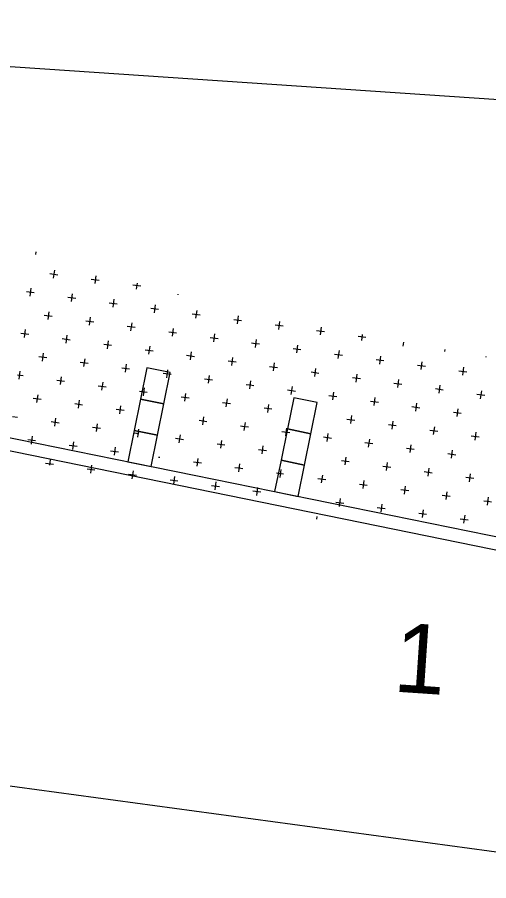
# Model space of a CAD drawing. Extents: x 1312564.5 to 1312581.5, y 1207298.4 to 1207309.4.
# Drawn here: x 1312577.003 to 1312577.548, y 1207303.846 to 1207304.843 of the extents above; entities that cross this region are included whole.
import ezdxf

# ---------------------------------------------------------------- set-up
doc = ezdxf.new("R2010")
doc.units = 0
for name, color, linetype in [('Level 15', 7, 'Continuous'), ('Level 2', 7, 'Continuous'), ('Level 20', 7, 'Continuous'), ('Level 3', 7, 'Continuous'), ('Level 4', 7, 'Continuous')]:
    doc.layers.add(name, color=color, linetype=linetype)

msp = doc.modelspace()

# ---------------------------------------------------------------- linework, layer by layer
at = {"layer": 'Level 15'}
msp.add_lwpolyline([(1312576.15065, 1207304.84261), (1312579.49796, 1207304.61698)], dxfattribs=at)
at = {"layer": 'Level 2'}
for p, q in [((1312576.95323, 1207304.36568), (1312579.00727, 1207303.94777)), ((1312579.00473, 1207303.93271), (1312576.95019, 1207304.35072))]:
    msp.add_line(p, q, dxfattribs=at)
for points in [[(1312577.14535, 1207304.40183), (1312577.17244, 1207304.39632), (1312577.17979, 1207304.43244), (1312577.1527, 1207304.43795)], [(1312577.138, 1207304.3657), (1312577.16509, 1207304.36019), (1312577.17244, 1207304.39632), (1312577.14535, 1207304.40183)], [(1312577.31505, 1207304.3673), (1312577.34215, 1207304.36179), (1312577.3495, 1207304.39791), (1312577.3224, 1207304.40342)], [(1312577.13065, 1207304.32958), (1312577.15774, 1207304.32407), (1312577.16509, 1207304.36019), (1312577.138, 1207304.3657)], [(1312577.3077, 1207304.33118), (1312577.3348, 1207304.32566), (1312577.34215, 1207304.36179), (1312577.31505, 1207304.3673)], [(1312577.30035, 1207304.29505), (1312577.32745, 1207304.28954), (1312577.3348, 1207304.32566), (1312577.3077, 1207304.33118)]]:
    msp.add_lwpolyline(points, close=True, dxfattribs=at)
at = {"layer": 'Level 3'}
msp.add_line((1312575.46594, 1207304.16215), (1312578.72454, 1207303.72084), dxfattribs=at)
at = {"layer": 'Level 4'}
for p, q in [((1312577.02429, 1207304.5717), (1312577.02389, 1207304.56865)), ((1312577.04585, 1207304.55063), (1312577.04463, 1207304.54149)), ((1312577.04067, 1207304.54667), (1312577.04981, 1207304.54545)), ((1312577.08857, 1207304.54026), (1312577.09771, 1207304.53904)), ((1312577.09375, 1207304.54421), (1312577.09253, 1207304.53508)), ((1312577.01869, 1207304.52989), (1312577.01747, 1207304.52075)), ((1312577.13647, 1207304.53384), (1312577.14561, 1207304.53262)), ((1312577.14134, 1207304.53547), (1312577.14043, 1207304.52867)), ((1312577.01352, 1207304.52593), (1312577.02265, 1207304.52471)), ((1312577.06142, 1207304.51952), (1312577.07055, 1207304.51829)), ((1312577.06659, 1207304.52347), (1312577.06537, 1207304.51434)), ((1312577.18843, 1207304.52301), (1312577.18833, 1207304.52225)), ((1312577.10932, 1207304.5131), (1312577.11845, 1207304.51188)), ((1312577.11449, 1207304.51706), (1312577.11327, 1207304.50792)), ((1312577.16239, 1207304.51064), (1312577.16117, 1207304.50151)), ((1312577.03426, 1207304.49877), (1312577.04339, 1207304.49755)), ((1312577.03944, 1207304.50273), (1312577.03821, 1207304.49359)), ((1312577.15722, 1207304.50669), (1312577.16635, 1207304.50546)), ((1312577.20512, 1207304.50027), (1312577.21425, 1207304.49905)), ((1312577.2103, 1207304.50423), (1312577.20907, 1207304.49509)), ((1312577.08216, 1207304.49236), (1312577.09129, 1207304.49114)), ((1312577.08734, 1207304.49631), (1312577.08611, 1207304.48718)), ((1312577.13524, 1207304.4899), (1312577.13401, 1207304.48077)), ((1312577.25302, 1207304.49386), (1312577.26215, 1207304.49264)), ((1312577.2582, 1207304.49781), (1312577.25697, 1207304.48868)), ((1312577.3061, 1207304.4914), (1312577.30487, 1207304.48227)), ((1312577.01228, 1207304.48199), (1312577.01106, 1207304.47285)), ((1312577.13006, 1207304.48594), (1312577.13919, 1207304.48472)), ((1312577.17796, 1207304.47953), (1312577.18709, 1207304.47831)), ((1312577.18314, 1207304.48349), (1312577.18191, 1207304.47435)), ((1312577.30092, 1207304.48744), (1312577.31005, 1207304.48622)), ((1312577.34882, 1207304.48103), (1312577.35795, 1207304.47981)), ((1312577.354, 1207304.48499), (1312577.35277, 1207304.47585)), ((1312577.0071, 1207304.47803), (1312577.01624, 1207304.47681)), ((1312577.055, 1207304.47162), (1312577.06414, 1207304.47039)), ((1312577.06018, 1207304.47557), (1312577.05896, 1207304.46644)), ((1312577.10808, 1207304.46916), (1312577.10686, 1207304.46002)), ((1312577.22586, 1207304.47312), (1312577.23499, 1207304.47189)), ((1312577.23104, 1207304.47707), (1312577.22981, 1207304.46794)), ((1312577.27894, 1207304.47066), (1312577.27771, 1207304.46152)), ((1312577.39672, 1207304.47462), (1312577.40585, 1207304.47339)), ((1312577.40159, 1207304.47631), (1312577.40067, 1207304.46944)), ((1312577.1029, 1207304.4652), (1312577.11204, 1207304.46398)), ((1312577.1508, 1207304.45879), (1312577.15994, 1207304.45756)), ((1312577.15598, 1207304.46274), (1312577.15476, 1207304.45361)), ((1312577.27376, 1207304.4667), (1312577.27833, 1207304.46609)), ((1312577.27833, 1207304.46609), (1312577.28289, 1207304.46548)), ((1312577.32166, 1207304.46029), (1312577.33079, 1207304.45906)), ((1312577.32684, 1207304.46424), (1312577.32562, 1207304.45511)), ((1312577.44916, 1207304.46744), (1312577.44857, 1207304.46302)), ((1312577.49679, 1207304.45897), (1312577.49647, 1207304.45661)), ((1312577.02784, 1207304.45087), (1312577.03698, 1207304.44965)), ((1312577.03302, 1207304.45483), (1312577.0318, 1207304.44569)), ((1312577.1987, 1207304.45237), (1312577.20784, 1207304.45115)), ((1312577.20388, 1207304.45633), (1312577.20266, 1207304.44719)), ((1312577.25178, 1207304.44991), (1312577.25056, 1207304.44078)), ((1312577.36956, 1207304.45387), (1312577.37869, 1207304.45265)), ((1312577.37474, 1207304.45783), (1312577.37352, 1207304.44869)), ((1312577.42264, 1207304.45141), (1312577.42142, 1207304.44228)), ((1312577.54446, 1207304.45086), (1312577.54437, 1207304.45019)), ((1312577.07574, 1207304.44446), (1312577.08488, 1207304.44324)), ((1312577.08092, 1207304.44841), (1312577.0797, 1207304.43928)), ((1312577.12882, 1207304.442), (1312577.1276, 1207304.43287)), ((1312577.2466, 1207304.44596), (1312577.25574, 1207304.44474)), ((1312577.2945, 1207304.43954), (1312577.30364, 1207304.43832)), ((1312577.29968, 1207304.4435), (1312577.29846, 1207304.43437)), ((1312577.41746, 1207304.44746), (1312577.42659, 1207304.44624)), ((1312577.46536, 1207304.44104), (1312577.47449, 1207304.43982)), ((1312577.47054, 1207304.445), (1312577.46932, 1207304.43587)), ((1312577.51844, 1207304.43859), (1312577.51722, 1207304.42945)), ((1312577.0032, 1207304.42979), (1312577.00982, 1207304.42891)), ((1312577.00587, 1207304.43409), (1312577.00464, 1207304.42495)), ((1312577.12364, 1207304.43804), (1312577.13278, 1207304.43682)), ((1312577.17154, 1207304.43163), (1312577.18068, 1207304.43041)), ((1312577.17672, 1207304.43559), (1312577.17551, 1207304.42655)), ((1312577.22462, 1207304.42917), (1312577.2234, 1207304.42004)), ((1312577.3424, 1207304.43313), (1312577.35154, 1207304.43191)), ((1312577.34758, 1207304.43709), (1312577.34636, 1207304.42795)), ((1312577.39548, 1207304.43067), (1312577.39426, 1207304.42154)), ((1312577.51326, 1207304.43463), (1312577.52239, 1207304.43341)), ((1312577.04859, 1207304.42372), (1312577.05772, 1207304.42249)), ((1312577.05377, 1207304.42767), (1312577.05254, 1207304.41854)), ((1312577.10167, 1207304.42126), (1312577.10044, 1207304.41212)), ((1312577.21944, 1207304.42522), (1312577.22858, 1207304.42399)), ((1312577.26735, 1207304.4188), (1312577.27191, 1207304.41819)), ((1312577.27252, 1207304.42276), (1312577.2713, 1207304.41362)), ((1312577.3903, 1207304.42672), (1312577.39944, 1207304.42549)), ((1312577.4382, 1207304.4203), (1312577.44734, 1207304.41908)), ((1312577.44338, 1207304.42426), (1312577.44216, 1207304.41512)), ((1312577.09649, 1207304.4173), (1312577.10562, 1207304.41608)), ((1312577.14439, 1207304.41089), (1312577.15305, 1207304.40973)), ((1312577.14957, 1207304.41484), (1312577.14834, 1207304.40571)), ((1312577.27191, 1207304.41819), (1312577.27648, 1207304.41758)), ((1312577.31525, 1207304.41239), (1312577.32438, 1207304.41116)), ((1312577.32042, 1207304.41634), (1312577.3192, 1207304.40721)), ((1312577.36832, 1207304.40993), (1312577.3671, 1207304.40079)), ((1312577.4861, 1207304.41389), (1312577.49524, 1207304.41266)), ((1312577.49128, 1207304.41784), (1312577.49006, 1207304.40871)), ((1312577.53918, 1207304.41143), (1312577.53796, 1207304.40229)), ((1312577.02143, 1207304.40297), (1312577.03056, 1207304.40175)), ((1312577.02661, 1207304.40693), (1312577.02539, 1207304.39779)), ((1312577.07451, 1207304.40051), (1312577.07329, 1207304.39138)), ((1312577.19229, 1207304.40447), (1312577.20142, 1207304.40325)), ((1312577.19747, 1207304.40843), (1312577.19624, 1207304.39929)), ((1312577.24537, 1207304.40201), (1312577.24414, 1207304.39288)), ((1312577.36315, 1207304.40597), (1312577.37228, 1207304.40475)), ((1312577.41105, 1207304.39956), (1312577.42018, 1207304.39834)), ((1312577.41622, 1207304.40351), (1312577.415, 1207304.39438)), ((1312577.534, 1207304.40747), (1312577.54314, 1207304.40625)), ((1312577.06933, 1207304.39656), (1312577.07846, 1207304.39534)), ((1312577.11723, 1207304.39014), (1312577.12636, 1207304.38892)), ((1312577.12241, 1207304.3941), (1312577.12119, 1207304.38497)), ((1312577.24019, 1207304.39806), (1312577.24932, 1207304.39684)), ((1312577.28809, 1207304.39164), (1312577.29722, 1207304.39042)), ((1312577.29327, 1207304.3956), (1312577.29204, 1207304.38647)), ((1312577.45895, 1207304.39314), (1312577.46808, 1207304.39192)), ((1312577.46412, 1207304.3971), (1312577.4629, 1207304.38797)), ((1312577.51202, 1207304.39069), (1312577.5108, 1207304.38155)), ((1312576.99735, 1207304.38182), (1312577.00341, 1207304.38101)), ((1312577.04735, 1207304.37977), (1312577.04613, 1207304.37064)), ((1312577.21821, 1207304.38127), (1312577.21699, 1207304.37214)), ((1312577.38389, 1207304.37882), (1312577.39302, 1207304.37759)), ((1312577.38907, 1207304.38277), (1312577.38784, 1207304.37364)), ((1312577.50685, 1207304.38673), (1312577.51598, 1207304.38551)), ((1312577.04217, 1207304.37582), (1312577.05131, 1207304.37459)), ((1312577.09007, 1207304.3694), (1312577.09921, 1207304.36818)), ((1312577.09525, 1207304.37336), (1312577.09403, 1207304.36422)), ((1312577.21303, 1207304.37732), (1312577.22217, 1207304.37609)), ((1312577.26093, 1207304.3709), (1312577.2655, 1207304.37029)), ((1312577.26611, 1207304.37486), (1312577.26489, 1207304.36572)), ((1312577.2655, 1207304.37029), (1312577.27007, 1207304.36968)), ((1312577.43179, 1207304.3724), (1312577.44092, 1207304.37118)), ((1312577.43697, 1207304.37636), (1312577.43574, 1207304.36722)), ((1312577.48487, 1207304.36994), (1312577.48364, 1207304.36081)), ((1312577.02019, 1207304.35903), (1312577.01897, 1207304.34989)), ((1312577.13797, 1207304.36299), (1312577.14346, 1207304.36225)), ((1312577.14315, 1207304.36694), (1312577.14193, 1207304.35781)), ((1312577.19105, 1207304.36053), (1312577.18983, 1207304.35139)), ((1312577.30883, 1207304.36449), (1312577.31797, 1207304.36326)), ((1312577.31401, 1207304.36844), (1312577.31279, 1207304.35931)), ((1312577.36191, 1207304.36203), (1312577.36069, 1207304.35289)), ((1312577.47969, 1207304.36599), (1312577.48882, 1207304.36476)), ((1312577.52759, 1207304.35957), (1312577.53672, 1207304.35835)), ((1312577.53277, 1207304.36353), (1312577.53154, 1207304.35439)), ((1312577.01502, 1207304.35507), (1312577.02415, 1207304.35385)), ((1312577.06809, 1207304.35261), (1312577.06687, 1207304.34348)), ((1312577.18587, 1207304.35657), (1312577.19501, 1207304.35535)), ((1312577.23377, 1207304.35016), (1312577.24291, 1207304.34894)), ((1312577.23895, 1207304.35411), (1312577.23773, 1207304.34498)), ((1312577.35673, 1207304.35807), (1312577.36587, 1207304.35685)), ((1312577.40463, 1207304.35166), (1312577.41377, 1207304.35044)), ((1312577.40981, 1207304.35561), (1312577.40859, 1207304.34648)), ((1312577.45771, 1207304.3492), (1312577.45649, 1207304.34007)), ((1312577.06292, 1207304.34866), (1312577.07205, 1207304.34744)), ((1312577.11082, 1207304.34224), (1312577.11995, 1207304.34102)), ((1312577.11599, 1207304.3462), (1312577.11477, 1207304.33707)), ((1312577.28167, 1207304.34374), (1312577.29081, 1207304.34252)), ((1312577.28685, 1207304.3477), (1312577.28563, 1207304.33857)), ((1312577.45253, 1207304.34524), (1312577.46167, 1207304.34402)), ((1312577.50043, 1207304.33883), (1312577.50957, 1207304.33761)), ((1312577.50561, 1207304.34279), (1312577.50439, 1207304.33365)), ((1312577.04094, 1207304.33187), (1312577.04008, 1207304.3255)), ((1312577.16613, 1207304.33484), (1312577.16785, 1207304.33461)), ((1312577.20662, 1207304.32942), (1312577.21575, 1207304.32819)), ((1312577.2118, 1207304.33337), (1312577.21057, 1207304.32424)), ((1312577.37747, 1207304.33092), (1312577.38661, 1207304.32969)), ((1312577.38265, 1207304.33487), (1312577.38143, 1207304.32574)), ((1312577.03576, 1207304.32792), (1312577.04489, 1207304.32669)), ((1312577.08366, 1207304.3215), (1312577.09279, 1207304.32028)), ((1312577.08884, 1207304.32546), (1312577.08761, 1207304.31632)), ((1312577.13674, 1207304.31904), (1312577.13551, 1207304.30991)), ((1312577.25452, 1207304.323), (1312577.25908, 1207304.32239)), ((1312577.2597, 1207304.32696), (1312577.25847, 1207304.31782)), ((1312577.25908, 1207304.32239), (1312577.26365, 1207304.32178)), ((1312577.3076, 1207304.32054), (1312577.30637, 1207304.31141)), ((1312577.42537, 1207304.3245), (1312577.43451, 1207304.32328)), ((1312577.43055, 1207304.32846), (1312577.42933, 1207304.31932)), ((1312577.47845, 1207304.32204), (1312577.47723, 1207304.31291)), ((1312577.13156, 1207304.31509), (1312577.14069, 1207304.31386)), ((1312577.18464, 1207304.31263), (1312577.18341, 1207304.30349)), ((1312577.30242, 1207304.31659), (1312577.3107, 1207304.31548)), ((1312577.35032, 1207304.31017), (1312577.35945, 1207304.30895)), ((1312577.3555, 1207304.31413), (1312577.35427, 1207304.30499)), ((1312577.47327, 1207304.31809), (1312577.48241, 1207304.31686)), ((1312577.52117, 1207304.31167), (1312577.53031, 1207304.31045)), ((1312577.52635, 1207304.31563), (1312577.52513, 1207304.30649)), ((1312577.17946, 1207304.30867), (1312577.18859, 1207304.30745)), ((1312577.22736, 1207304.30226), (1312577.23649, 1207304.30104)), ((1312577.23254, 1207304.30621), (1312577.23132, 1207304.29708)), ((1312577.28044, 1207304.2998), (1312577.27922, 1207304.29067)), ((1312577.39822, 1207304.30376), (1312577.40735, 1207304.30254)), ((1312577.4034, 1207304.30771), (1312577.40217, 1207304.29858)), ((1312577.4513, 1207304.3013), (1312577.45007, 1207304.29217)), ((1312577.27526, 1207304.29584), (1312577.28439, 1207304.29462)), ((1312577.44612, 1207304.29734), (1312577.45525, 1207304.29612)), ((1312577.49402, 1207304.29093), (1312577.50315, 1207304.28971)), ((1312577.4992, 1207304.29489), (1312577.49797, 1207304.28575)), ((1312577.37106, 1207304.28302), (1312577.38019, 1207304.28179)), ((1312577.37624, 1207304.28697), (1312577.37502, 1207304.27784)), ((1312577.42414, 1207304.28056), (1312577.42292, 1207304.27142)), ((1312577.54192, 1207304.28452), (1312577.54648, 1207304.2839)), ((1312577.5471, 1207304.28847), (1312577.54587, 1207304.27934)), ((1312577.54648, 1207304.2839), (1312577.55105, 1207304.28329)), ((1312577.41896, 1207304.2766), (1312577.42809, 1207304.27538)), ((1312577.46686, 1207304.27019), (1312577.47599, 1207304.26896)), ((1312577.47204, 1207304.27414), (1312577.47082, 1207304.26501)), ((1312577.34908, 1207304.26623), (1312577.34868, 1207304.26319)), ((1312577.51476, 1207304.26377), (1312577.52389, 1207304.26255)), ((1312577.51994, 1207304.26773), (1312577.51872, 1207304.25859))]:
    msp.add_line(p, q, dxfattribs=at)

# ---------------------------------------------------------------- texts
at = {"layer": 'Level 20'}
msp.add_text('1', height=0.08, rotation=356.1437, dxfattribs=at).set_placement((1312577.43638, 1207304.0643))

doc.saveas('drawing.dxf')
